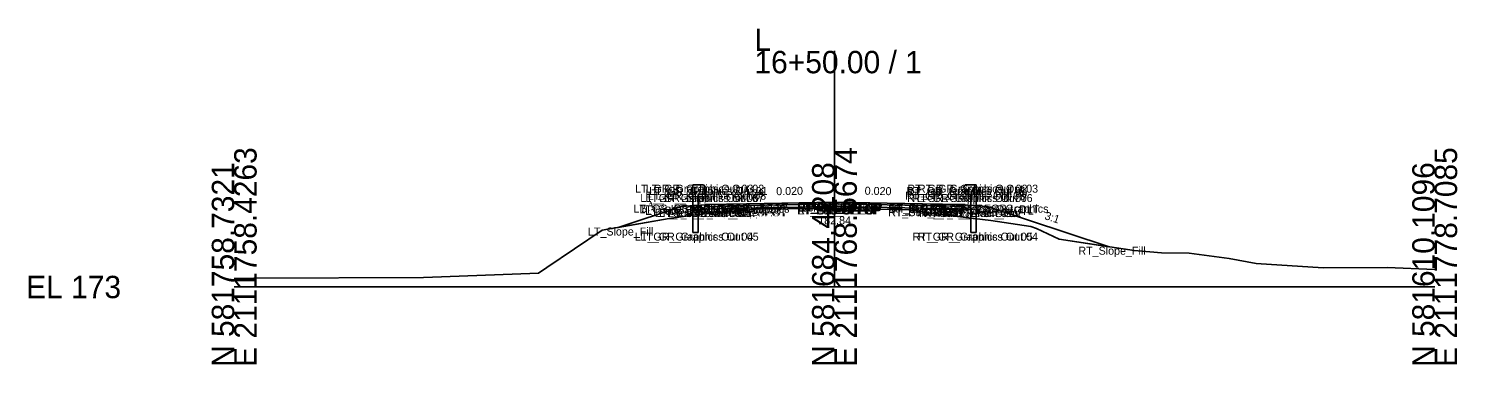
# Model space of a CAD drawing. Extents: x -486 to 1153, y -333 to 9539.
# Drawn here: x -25.7 to 152.8, y 6990.3 to 7032.3 of the extents above; entities that cross this region are included whole.
import ezdxf

# ---------------------------------------------------------------- set-up
doc = ezdxf.new("R2010")
doc.units = 0
for name, color, linetype in [('Default', 7, 'Continuous'), ('Exist Cross Section Cell', 7, 'Continuous'), ('Exist XS Ground Line', 7, 'Continuous'), ('Prop CMT Guardrail Graphics', 7, 'Continuous'), ('Prop CMT Pvmt Course 1', 7, 'Continuous'), ('Prop CMT Pvmt Course 2', 7, 'Continuous'), ('Prop CMT Pvmt Course 3', 7, 'Continuous'), ('Prop CMT Pvmt Surface', 7, 'Continuous'), ('Prop CMT Pvmt Surface Shoulder', 7, 'Continuous'), ('Prop CMT Shld Paved Course 1', 7, 'Continuous'), ('Prop CMT Shld Paved Course 2', 7, 'Continuous'), ('Prop CMT Shld Paved Course 3', 7, 'Continuous'), ('Prop CMT Slope Grass', 7, 'Continuous'), ('Prop CMT Subgrade Earthwork', 7, 'Continuous'), ('Prop XS Earthwork Shape', 7, 'Continuous'), ('Prop XS SE Text', 7, 'Continuous'), ('Prop XS Side Slope Text', 7, 'Continuous'), ('Scratch_Level_0', 7, 'Continuous')]:
    doc.layers.add(name, color=color, linetype=linetype)

msp = doc.modelspace()

# ---------------------------------------------------------------- linework, layer by layer
at = {"layer": 'Exist Cross Section Cell'}
for p, q in [((75, 7000), (75, 7029.54)), ((0, 7000), (75, 7000)), ((75, 7000), (150, 7000))]:
    msp.add_line(p, q, dxfattribs=at)
at = {"layer": 'Exist XS Ground Line'}
for p, q in [((57.62, 7009.01), (65.26, 7009.73)), ((65.26, 7009.73), (73.01, 7009.83)), ((73.01, 7009.83), (74.68, 7009.85)), ((74.68, 7009.85), (75, 7009.84)), ((75, 7009.84), (76.36, 7009.81)), ((76.36, 7009.81), (84.28, 7009.66)), ((84.28, 7009.66), (87.61, 7009.15)), ((45.96, 7007.09), (54.35, 7008.57)), ((54.35, 7008.57), (57.62, 7009.01)), ((87.61, 7009.15), (94.54, 7008.33)), ((94.54, 7008.33), (99.54, 7007.59)), ((99.54, 7007.59), (100.26, 7007.33)), ((39.05, 7002.45), (45.96, 7007.09)), ((100.26, 7007.33), (103.09, 7005.99)), ((103.09, 7005.99), (112.44, 7004.56)), ((112.44, 7004.56), (115.86, 7004.28)), ((115.86, 7004.28), (119.34, 7004.22)), ((119.34, 7004.22), (124.34, 7003.55)), ((38.03, 7001.74), (39.05, 7002.45)), ((124.34, 7003.55), (127.68, 7002.96)), ((127.68, 7002.96), (136.07, 7002.38)), ((136.07, 7002.38), (144.07, 7002.42)), ((144.07, 7002.42), (150, 7002.18)), ((0, 7001.07), (0.4, 7001.06)), ((0.4, 7001.06), (2.45, 7001.09)), ((2.45, 7001.09), (23.65, 7001.2)), ((23.65, 7001.2), (25.91, 7001.29)), ((25.91, 7001.29), (38.03, 7001.74))]:
    msp.add_line(p, q, dxfattribs=at)
at = {"layer": 'Prop CMT Guardrail Graphics'}
for points in [[(57.3, 7006.8), (57.3, 7012.8)], [(57.3, 7012.8), (58.63, 7012.8), (58.9, 7012.51)], [(92.7, 7012.8), (91.37, 7012.8), (91.1, 7012.51)], [(92.7, 7006.8), (92.7, 7012.8)], [(58.9, 7011.92), (58.63, 7011.63), (57.96, 7011.63)], [(57.96, 7011.63), (57.96, 7006.8)], [(58.9, 7012.51), (58.63, 7012.21)], [(58.63, 7012.21), (58.9, 7011.92)], [(91.1, 7012.51), (91.37, 7012.21)], [(91.37, 7012.21), (91.1, 7011.92)], [(91.1, 7011.92), (91.37, 7011.63), (92.04, 7011.63)], [(92.04, 7011.63), (92.04, 7006.8)], [(57.96, 7006.8), (57.3, 7006.8)], [(92.04, 7006.8), (92.7, 7006.8)]]:
    msp.add_lwpolyline(points, dxfattribs=at)
at = {"layer": 'Prop CMT Pvmt Course 1'}
for points in [[(75, 7010.63), (64, 7010.41)], [(64, 7010.2), (75, 7010.42)], [(64, 7010.41), (64, 7010.2)], [(75, 7010.42), (75, 7010.63)], [(75, 7010.63), (86, 7010.41)], [(75, 7010.42), (75, 7010.63)], [(86, 7010.2), (75, 7010.42)], [(86, 7010.41), (86, 7010.2)]]:
    msp.add_lwpolyline(points, dxfattribs=at)
msp.add_lwpolyline([(75, 7010.42), (75, 7010.5), (75, 7010.5), (75, 7010.42)], close=True, dxfattribs=at)
msp.add_lwpolyline([(75, 7010.42), (75, 7010.5), (75, 7010.5), (75, 7010.42)], close=True, dxfattribs=at)
at = {"layer": 'Prop CMT Pvmt Course 2'}
for points in [[(75, 7010.42), (64, 7010.2)], [(64, 7010.2), (64, 7009.86)], [(64, 7009.86), (75, 7010.08)], [(75, 7010.08), (75, 7010.42)], [(75, 7010.08), (75, 7010.42)], [(75, 7010.42), (86, 7010.2)], [(86, 7009.86), (75, 7010.08)], [(86, 7010.2), (86, 7009.86)]]:
    msp.add_lwpolyline(points, dxfattribs=at)
at = {"layer": 'Prop CMT Pvmt Course 3'}
for points in [[(75, 7010.08), (64, 7009.86)], [(64, 7009.86), (64, 7009.86)], [(75, 7010.08), (75, 7010.08)], [(75, 7010.08), (86, 7009.86)], [(75, 7010.08), (75, 7010.08)], [(86, 7009.86), (86, 7009.86)]]:
    msp.add_lwpolyline(points, dxfattribs=at)
at = {"layer": 'Prop CMT Pvmt Surface'}
for points in [[(75, 7010.63), (64, 7010.41)], [(75, 7010.63), (86, 7010.41)]]:
    msp.add_lwpolyline(points, dxfattribs=at)
at = {"layer": 'Prop CMT Pvmt Surface Shoulder'}
for points in [[(64, 7010.41), (59, 7010.31)], [(86, 7010.41), (91, 7010.31)]]:
    msp.add_lwpolyline(points, dxfattribs=at)
at = {"layer": 'Prop CMT Shld Paved Course 1'}
for points in [[(64, 7010.41), (59, 7010.31), (58.79, 7010.09)], [(58.79, 7010.09), (64, 7010.2)], [(64, 7010.2), (64, 7010.41)], [(86, 7010.41), (91, 7010.31), (91.21, 7010.09)], [(86, 7010.2), (86, 7010.41)], [(91.21, 7010.09), (86, 7010.2)]]:
    msp.add_lwpolyline(points, dxfattribs=at)
at = {"layer": 'Prop CMT Shld Paved Course 2'}
for points in [[(64, 7010.2), (58.79, 7010.09), (58.45, 7009.75)], [(58.45, 7009.75), (64, 7009.86)], [(64, 7009.86), (64, 7010.2)], [(86, 7010.2), (91.21, 7010.09), (91.55, 7009.75)], [(86, 7009.86), (86, 7010.2)], [(91.55, 7009.75), (86, 7009.86)]]:
    msp.add_lwpolyline(points, dxfattribs=at)
at = {"layer": 'Prop CMT Shld Paved Course 3'}
for points in [[(64, 7009.86), (58.45, 7009.75)], [(58.45, 7009.75), (58.45, 7009.75), (58.45, 7009.75)], [(64, 7009.86), (64, 7009.86)], [(86, 7009.86), (91.55, 7009.75)], [(86, 7009.86), (86, 7009.86)], [(91.55, 7009.75), (91.55, 7009.75), (91.55, 7009.75)]]:
    msp.add_lwpolyline(points, dxfattribs=at)
at = {"layer": 'Prop CMT Slope Grass'}
for points in [[(55.9, 7010.06), (47.97, 7007.44)], [(58.9, 7010.3), (55.9, 7010.06)], [(59, 7010.31), (58.9, 7010.3)], [(91, 7010.31), (91.1, 7010.3)], [(91.1, 7010.3), (94.1, 7010.06)], [(94.1, 7010.06), (109.31, 7005.04)]]:
    msp.add_lwpolyline(points, dxfattribs=at)
at = {"layer": 'Prop CMT Subgrade Earthwork'}
for points in [[(58.45, 7009.75), (57.98, 7010.22)], [(64, 7009.86), (58.45, 7009.75)], [(75, 7010.08), (64, 7009.86)], [(75, 7010.08), (86, 7009.86)], [(86, 7009.86), (91.55, 7009.75)], [(91.55, 7009.75), (92.02, 7010.22)]]:
    msp.add_lwpolyline(points, dxfattribs=at)
at = {"layer": 'Prop XS Earthwork Shape'}
msp.add_lwpolyline([(65.26, 7009.73), (73.01, 7009.83), (74.68, 7009.85), (75, 7009.84), (76.36, 7009.81), (84.28, 7009.66), (87.61, 7009.15), (94.54, 7008.33), (99.54, 7007.59), (100.26, 7007.33), (103.09, 7005.99), (109.31, 7005.04), (94.1, 7010.06), (92.02, 7010.22), (91.55, 7009.75), (86, 7009.86), (75, 7010.08), (64, 7009.86), (58.45, 7009.75), (57.98, 7010.22), (55.9, 7010.06), (47.97, 7007.44), (54.35, 7008.57), (57.62, 7009.01)], close=True, dxfattribs=at)

# ---------------------------------------------------------------- texts
at = {"layer": 'Default'}
for s, height, p in [('182.84', 1, (72.98, 7007.84)), ('-', 0.0001, (0, 7000))]:
    msp.add_text(s, height=height, dxfattribs=at).set_placement(p)
at = {"layer": 'Exist Cross Section Cell'}
for s, p in [('L', (65, 7029.54)), ('16+50.00 / 1', (65, 7026.74)), ('EL 173', (-26, 6998.6))]:
    msp.add_text(s, height=2.8, dxfattribs=at).set_placement(p)
for s, p in [('E 2111758.4263', (2.8, 6990)), ('E 2111768.5674', (77.8, 6990)), ('E 2111778.7085', (152.8, 6990)), ('N 581758.7321', (0, 6990)), ('N 581684.4208', (75, 6990)), ('N 581610.1096', (150, 6990))]:
    msp.add_text(s, height=2.8, rotation=90, dxfattribs=at).set_placement(p)
at = {"layer": 'Prop XS SE Text'}
for rotation, p in [(1.1458, (67.73, 7011.48)), (358.8542, (78.77, 7011.55))]:
    msp.add_text('0.020', height=1, rotation=rotation, dxfattribs=at).set_placement(p)
at = {"layer": 'Prop XS Side Slope Text'}
for rotation, p in [(18.2629, (50.95, 7009.21)), (341.7371, (101.18, 7008.51))]:
    msp.add_text('3:1', height=1, rotation=rotation, dxfattribs=at).set_placement(p)
at = {"layer": 'Scratch_Level_0'}
for s, p in [('LT_GR_Graphics Out 03', (50.08, 7011.8)), ('LT_GR_Graphics Out 02', (51.43, 7011.8)), ('RT_GR_Graphics Out 02', (84.11, 7011.8)), ('RT_GR_Graphics Out 03', (85.43, 7011.8)), ('LT_GR_Graphics Out 06', (50.74, 7010.63)), ('LT_GR_Graphics Out 07', (51.39, 7010.63)), ('LT_GR_Graphics Out 09', (51.4, 7011.21)), ('LT_GR_Graphics Out 08', (51.67, 7010.92)), ('LT_GR_Graphics Out 01', (51.85, 7011.51)), ('RT_GR_Graphics Out 08', (83.81, 7010.92)), ('RT_GR_Graphics Out 01', (83.99, 7011.51)), ('RT_GR_Graphics Out 07', (84.07, 7010.63)), ('RT_GR_Graphics Out 09', (84.09, 7011.21)), ('RT_GR_Graphics Out 06', (84.75, 7010.63)), ('LT_GS_OS_GR_Face_Graphics', (49.9, 7009.3)), ('LT_Sub_Trench_Out_DLT', (50.63, 7009.22)), ('LT_GS_OS_CTL', (51.36, 7009.06)), ('LT_Sub_Trench_Out', (52.56, 7008.75)), ('LT_PS3_Shelf_Out', (53.1, 7008.75)), ('LT_PS3_OEOP', (54.23, 7008.75)), ('LT_PS2_OEOP', (54.57, 7009.09)), ('LT_PS1_OEOP', (54.91, 7009.31)), ('LT_PV2_OEOT', (59.75, 7009.2)), ('LT_PV3_OEOT', (59.75, 7008.86)), ('LT_Sub_OEOT', (59.77, 7008.86)), ('LT_PV1_OEOT', (59.87, 7009.41)), ('RT_PV2_OEEOP', (70.33, 7009.42)), ('RT_PV3_OEEOP', (70.33, 7009.08)), ('RT_Sub_OEEOP', (70.36, 7009.08)), ('LT_PV2_OEEOP', (70.39, 7009.42)), ('LT_PV3_OEEOP', (70.39, 7009.08)), ('LT_Sub_OEEOP', (70.42, 7009.08)), ('RT_PV1_OEEOP', (70.45, 7009.5)), ('LT_PV1_OEEOP', (70.51, 7009.5)), ('RT_PV2_IEEOP', (70.71, 7009.42)), ('LT_PV2_IEEOP', (70.77, 7009.42)), ('RT_PV1_IEEOP', (70.83, 7009.5)), ('LT_PV1_IEEOP', (70.89, 7009.5)), ('PV2_PGL', (72.35, 7009.42)), ('PV1_PGL', (72.47, 7009.63)), ('RT_PV2_OEOT', (81.69, 7009.2)), ('RT_PV3_OEOT', (81.69, 7008.86)), ('RT_Sub_OEOT', (81.71, 7008.86)), ('RT_PV1_OEOT', (81.81, 7009.41)), ('RT_GS_OS_GR_Face_Graphics', (82.04, 7009.3)), ('RT_Sub_Trench_Out_DLT', (84.61, 7009.22)), ('RT_Sub_Trench_Out', (85.6, 7008.75)), ('RT_PS3_Shelf_Out', (86.15, 7008.75)), ('RT_PS1_OEOP', (86.85, 7009.31)), ('RT_PS2_OEOP', (86.94, 7009.09)), ('RT_PS3_OEOP', (87.28, 7008.75)), ('RT_GS_OS_CTL', (89.5, 7009.06)), ('LT_Slope_Fill', (44.2, 7006.44)), ('LT_GR_Graphics Out 04', (50.07, 7005.8)), ('LT_GR_Graphics Out 05', (50.74, 7005.8)), ('RT_GR_Graphics Out 05', (84.76, 7005.8)), ('RT_GR_Graphics Out 04', (85.41, 7005.8)), ('RT_Slope_Fill', (105.48, 7004.04))]:
    msp.add_text(s, height=1, dxfattribs=at).set_placement(p)

doc.saveas('drawing.dxf')
